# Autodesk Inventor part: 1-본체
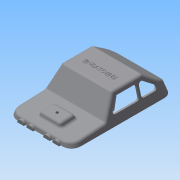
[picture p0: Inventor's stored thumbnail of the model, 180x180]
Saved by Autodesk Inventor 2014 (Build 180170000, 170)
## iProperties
Created: 2015-05
Part Number: 1-본체
Material: Generic
Document SubType Name: Modeling
Designer: Administrator
Density: 1 g/cm^3
Appearance: Default
Author: Administrator
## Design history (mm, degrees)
sketch "스케치1"
  geometry: L1 (-61, 0)-(61, 0); L2 (61, 0)-(58.321, -10); L3 (-61, 0)-(-59.66, -5); L4 (-59.66, -5)-(-19, -7.131); L5 (-19, -7.131)-(-4.71, -30); L6 (-4.71, -30)-(31, -30); L7 (31, -30)-(58.321, -10); 2 further points
  constraints: 14 end point, 1 coincident, 1 horizontal, 1 midpoint, 1 parallel
  dimensions: "d28" = 122 distance of L1.start L1.end; "d29" = 105 deg angle of L1 L2; "d30" = 105 deg angle of L1 L3; "d31" = 3 deg angle of L1 L4; "d32" = 5 vertical distance of L1.start L3.end; "d33" = 125 deg angle of L5 L4; "d34" = 42 horizontal distance of L4.end L1.start; "d35" = 30 distance between parallel lines of L1 L6; "d36" = 30 horizontal distance of L1.end L6.end; "d37" = 20 vertical distance of L2.end L6.end
extrude "돌출1" new body sketch "스케치1" stored distance "d12" = 76; taper "d13" = 0 deg
node "작업 평면1"
sketch "스케치2"
  geometry: L1 (0, 38)-(0, -38) reference; L2 (-30, 38)-(-30, -38) reference; L3 (0, -38)-(-30, -29.962); L4 (0, 38)-(-30, 29.962); L5 (-30, -38)-(0, -38); L6 (-30, 38)-(0, 38); 3 further points
  constraints: 8 end point, 2 point on line, 1 parallel, 1 perpendicular
  dimensions: "d39" = 105 deg angle of L1 L3; "d40" = 105 deg angle of L1 L4
extrude "돌출2" cut sketch "스케치2" stored distance "d41" = 76; taper "d42" = 0 deg
sketch "스케치4"
  geometry: L1 (-59.66, -5)-(-19, -7.131) reference; L2 (-50.015, -5.505)-(-48.459, -10.594); L3 (-48.459, -10.594)-(-32.122, -11.45); L4 (-32.122, -11.45)-(-30.042, -6.552); 1 further point
  constraints: 6 end point, 2 point on line, 1 parallel
  dimensions: "d65" = 20 distance of L4.end L2.start
extrude "돌출4" join sketch "스케치4" stored distance "d68" = 26; taper "d69" = 0 deg
fillet "모깎기6" dims "d139" = 12
fillet "모깎기2" dims "d101" = 3
fillet "모깎기3" dims "d102" = 3
fillet "모깎기4" dims "d103" = 3
fillet "모깎기5" dims "d104" = 3
feature "쉘1" dims "d43" = 2
sketch "스케치3"
  geometry: L1 (-58.321, -10)-(-31, -30) reference; L2 (-31, -30)-(4.71, -30) reference; L3 (4.71, -30)-(19, -7.131) reference; L4 (2.819, -23.59)-(8.443, -14.59); L5 (5.899, -10)-(-19.689, -10); L6 (-22.689, -13)-(-22.689, -22); L7 (-19.689, -25)-(0.275, -25); L8 (-25.385, -22)-(-25.385, -13); L9 (-28.385, -10)-(-40.679, -10); L10 (-30.157, -24.421)-(-42.451, -15.421); A1 r 3 centre (5.899, -13) between (8.443, -14.59) and (5.899, -10); A2 r 3 centre (0.275, -22) between (0.275, -25) and (2.819, -23.59); A3 r 3 centre (-19.689, -13) between (-19.689, -10) and (-22.689, -13); A4 r 3 centre (-19.689, -22) between (-22.689, -22) and (-19.689, -25); A5 r 3 centre (-28.385, -22) between (-30.157, -24.421) and (-25.385, -22); A6 r 3 centre (-28.385, -13) between (-25.385, -13) and (-28.385, -10); A7 r 3 centre (-40.679, -13) between (-40.679, -10) and (-42.451, -15.421); 2 further points
  constraints: 14 end point, 14 point on circle, 14 tangent, 7 centre point, 4 perpendicular, 3 equal radius, 3 parallel, 2 point on line
  dimensions: "d45" = 5 distance between parallel lines of L3 L4; "d46" = 15 distance between parallel lines of L5 L7; "d47" = 34 distance from line of L6 point (11.311, -10); "d48" = 3 radius of A1; "d53" = 5 distance between parallel lines of L2 L7; "d54" = 3 radius of A5; "d55" = 5 distance edge to line of A5 L2; "d56" = 15 dimension on A5 L9; "d57" = 3 radius of A6; "d58" = 5 distance between parallel lines of L1 L10; "d59" = 3 radius of A7
extrude "돌출3" cut sketch "스케치3" stored distance "d60" = 76; taper "d61" = 0 deg
sketch "스케치6"
  geometry: L1 (-61, 38)-(-61, -38) reference; C1 r 3 at (-40, 0); C2 r 3 at (40, 0); C3 r 3 at (0, -22); C4 r 3 at (0, 22); 3 further points
  constraints: 4 centre point, 2 equal radius, 2 horizontal alignment, 1 vertical alignment
  dimensions: "d74" = 6 diameter of C2; "d75" = 6 diameter of C1; "d76" = 21 distance from line of C1.centre L1; "d77" = 40 horizontal distance of C3.centre C1.centre; "d78" = 40 horizontal distance of C2.centre C3.centre; "d79" = 44 distance of C4.centre C3.centre; "d80" = 22 distance of C3.centre point (0, 0)
extrude "돌출6" join sketch "스케치6" stored distance "d81" = 1; taper "d82" = 2 deg
node "작업 평면2"
sketch "스케치8"
  geometry: L1 (0, 26.409)-(0, 38) reference; L2 (0, -38)-(0, -26.409) reference; L3 (0, 25)-(0, 17); L4 (0, 14)-(0, 6); L5 (0, -6)-(0, -14); L6 (0, -17)-(0, -25); A1 r 4 centre (0, 10) between (0, 6) and (0, 14); A2 r 4 centre (0, 21) between (0, 17) and (0, 25); A3 r 4 centre (0, -10) between (0, -14) and (0, -6); A4 r 4 centre (0, -21) between (0, -25) and (0, -17); 1 further point
  constraints: 8 end point, 8 point on circle, 4 centre point, 3 equal radius, 13 other
  dimensions: "d106" = 10 distance of A1.centre point (0, 0); "d108" = 4 radius of A1; "d109" = 11 distance of A2.centre A1.centre; "d110" = 20 distance of A3.centre A1.centre; "d111" = 11 distance of A4.centre A3.centre
extrude "돌출8" join sketch "스케치8" distance "d112" = 3.5; taper "d113" = 0 deg
sketch "스케치11"
  geometry: L1 (-45, -2)-(-35, -2); L2 (-35, -2)-(-33.557, -10.181); L3 (-33.557, -10.181)-(-46.443, -10.181); L4 (-46.443, -10.181)-(-45, -2); L5 (35, -2)-(45, -2); L6 (45, -2)-(47.646, -17.004); L7 (35, -2)-(30.088, -29.857); L8 (30.157, -24.421)-(42.451, -15.421) reference; L9 (40.679, -10)-(28.385, -10) reference; L10 (25.385, -13)-(25.385, -22) reference; L11 (19.689, -10)-(-5.899, -10) reference; L12 (-8.443, -14.59)-(-2.819, -23.59) reference; L13 (-0.275, -25)-(19.689, -25) reference; L14 (22.689, -22)-(22.689, -13) reference; L15 (-49.409, 0)-(49.409, 0) reference; L16 (-37, 0)-(-36.678, -9.209) reference; L17 (-43, 0)-(-43.309, -8.861) reference; L18 (37, 0)-(36.171, -23.736) reference; L19 (43, 0)-(43.638, -18.27) reference; L20 (30.088, -29.857)-(47.646, -17.004); L21 (-48.509, -3.357)-(-20.403, -4.83) reference; L22 (-49.409, 0)-(-48.509, -3.357) reference; L23 (44.881, -16.897)-(49.409, 0) reference; L24 (30.019, -27.776)-(44.881, -16.897) reference; L25 (-3.047, -27.776)-(30.019, -27.776) reference; L26 (-15.628, -7.642)-(-3.047, -27.776) reference; A1 r 3 centre (28.385, -22) between (25.385, -22) and (30.157, -24.421) reference; A2 r 3 centre (40.679, -13) between (42.451, -15.421) and (40.679, -10) reference; A3 r 3 centre (28.385, -13) between (28.385, -10) and (25.385, -13) reference; A4 r 3 centre (19.689, -13) between (22.689, -13) and (19.689, -10) reference; A5 r 3 centre (-5.899, -13) between (-5.899, -10) and (-8.443, -14.59) reference; A6 r 3 centre (-0.275, -22) between (-2.819, -23.59) and (-0.275, -25) reference; A7 r 3 centre (19.689, -22) between (19.689, -25) and (22.689, -22) reference; A8 r 6 centre (-20.717, -10.822) between (-15.628, -7.642) and (-20.403, -4.83) reference; 7 further points
  constraints: 16 end point, 3 parallel, 2 coincident, 1 horizontal, 1 other
  dimensions: "d115" = 80 deg angle to the sketch x axis of L4; "d116" = 80 deg angle to the sketch x axis of L2; "d117" = 2 distance of the line from the sketch origin of L1; "d118" = 2 horizontal distance of point (-37, 0) L1.end; "d119" = 2 horizontal distance of point (-43, 0) L1.start; "d120" = 12.8852 distance of L2.end L3.end; "d121" = 2 horizontal distance of L18.start L5.start; "d122" = 2 horizontal distance of L19.start L5.end; "d123" = 80 deg angle to the sketch x axis of L7; "d124" = 2 distance of the line from the sketch origin of L5; "d125" = 21.75929 distance of L7.end L6.end
extrude "돌출9" join sketch "스케치11" stored distance "d126" = 2; taper "d127" = 0 deg
node "작업 평면4"
node "작업 평면5"
sketch "스케치12"
  geometry: L1 (-61.287, 7.01)-(-51.287, 7.01); L2 (-51.287, 7.01)-(-46.532, -19.954); L3 (-61.287, 7.01)-(-64.014, -8.455); L4 (-105.696, 9.01)-(-6.878, 9.01) reference; L5 (-59.287, 9.01)-(-60.245, -18.419) reference; L6 (-64.014, -8.455)-(-64.793, -12.874); L7 (-64.793, -12.874)-(-60.29, -19.474); L8 (-60.29, -19.474)-(-46.532, -19.954); 6 further points
  constraints: 12 end point, 1 coincident, 1 collinear, 1 horizontal, 1 perpendicular
  dimensions: "d129" = 80 deg angle of L4 L3; "d130" = 80 deg angle of L4 L2; "d131" = 10 distance of L1.start L1.end; "d132" = 2 distance between parallel lines of L4 L1; "d133" = 2 horizontal distance of L1.start point (-59.287, 9.01); "d134" = 13.75762 horizontal distance of L7.end L2.end; "d135" = 6.59969 vertical distance of L6.end L7.end; "d136" = 18.26068 horizontal distance of L2.end L6.end
extrude "돌출10" join sketch "스케치12" stored distance "d137" = 2; taper "d138" = 0 deg
sketch "스케치13"
  geometry: L1 (64.047, 54.068)-(64.047, 1.251) reference; 2 further points
  constraints: 1 horizontal alignment, 1 other
  dimensions: "d140" = 50 distance from line of L1 point (14.047, 27.66)
feature "엠보싱1" sketch "스케치13" dims "d141" = 0.5, "d142" = 0
sketch "스케치14"
  geometry: C1 r 3 at (0, 0) reference; C2 r 3 at (-40, -22) reference; C3 r 3 at (0, -44) reference; C4 r 3 at (40, -22) reference; 4 further points
  constraints: 3 coincident
hole "구멍1" sketch "스케치14" at (0, -44), (40, -22), (0, 0) diameter "d143" = 3.242; stored, may be unused: countersink angle "d147" = 90 deg, drill point angle "d149" = 118 deg; dims "d144" = 9, "d145" = 4, "d146" = 2, "d148" = 11
sketch "스케치15"
  geometry: L1 (0.139, 73.929)-(98.679, 73.929) reference; L2 (108.338, 64.27)-(108.338, 11.73) reference; L3 (98.679, 2.071)-(0.139, 2.071) reference; L4 (-9.521, 11.73)-(-9.521, 64.27) reference; L5 (98.679, 74.929)-(0.139, 74.929); L6 (-10.521, 64.27)-(-10.521, 11.73); L7 (0.139, 1.071)-(98.679, 1.071); L8 (109.338, 11.73)-(109.338, 64.27); 5 further points; 4 other entities
  constraints: 8 end point, 7 parallel, 16 other
  dimensions: "d150" = 1 distance between parallel lines of L1 L5
extrude "돌출11" join sketch "스케치15" distance "d151" = 1; taper "d152" = 0 deg
hole "구멍2" diameter "d155" = 3.242; stored, may be unused: countersink angle "d159" = 90 deg, drill point angle "d161" = 118 deg; dims "d153" = 10, "d154" = 10, "d156" = 9, "d157" = 4, "d158" = 2, "d160" = 11
node "솔리드1"
mirror "대칭1"
node "투영된 루프7"
node "투영된 루프8"
node "투영된 루프9"
node "투영된 루프10"
other parameters: "d38" = 61, "d105" = -63, "d128" = -22
